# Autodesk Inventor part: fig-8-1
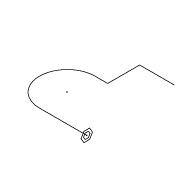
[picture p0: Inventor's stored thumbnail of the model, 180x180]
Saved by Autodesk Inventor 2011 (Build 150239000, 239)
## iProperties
Created: 2004-05
Part Number: fig-8-1
Document SubType Name: Modeling
Designer: CADCIM Technologies
Manufacturer: Standard
Standards Organization: Custom
Density: 1 g/cm^3
Author: CADCIM Technologies
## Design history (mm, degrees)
sketch "Sketch1"
  geometry: L1 (-42.583, 3.219)-(-90.066, 3.219); L2 (-90.066, 58.92)-(-77.282, 58.92); L3 (-77.282, 58.92)-(-77.282, 91.063); L4 (-77.282, 91.063)-(-42.583, 91.063); A1 r 27.851 centre (-90.066, 31.07) between (-90.066, 58.92) and (-90.066, 3.219)
  constraints: 8 end point, 2 parallel, 2 point on circle, 2 tangent, 1 centre point, 1 perpendicular
workplane "Work Plane2"
sketch "Sketch2"
  geometry: L1 (-5.697, 0)-(-2.849, 4.934); L2 (-2.849, 4.934)-(2.849, 4.934); L3 (2.849, 4.934)-(5.697, 0); L4 (5.697, 0)-(2.849, -4.934); L5 (2.849, -4.934)-(-2.849, -4.934); L6 (-2.849, -4.934)-(-5.697, 0); L7 (-3.256, 0)-(-1.628, 2.819); L8 (-1.628, 2.819)-(1.628, 2.819); L9 (1.628, 2.819)-(3.256, 0); L10 (3.256, 0)-(1.628, -2.819); L11 (1.628, -2.819)-(-1.628, -2.819); L12 (-1.628, -2.819)-(-3.256, 0); 2 further points
  constraints: 24 end point, 1 coincident, 22 other
